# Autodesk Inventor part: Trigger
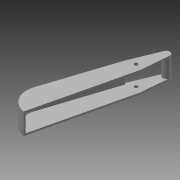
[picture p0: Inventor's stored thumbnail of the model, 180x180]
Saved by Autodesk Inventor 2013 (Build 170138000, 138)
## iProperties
Created: 2009-03
Part Number: Trigger
Document SubType Name: Modeling
Designer: tangg
Density: 7.85 g/cm^3
Material: Steel
Mass: 29.3702 g
Surface Area: 74.34 cm^2
Volume: 3.74142 cm^3
Author: tangg
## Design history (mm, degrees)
sketch "Sketch1"
  geometry: L1 (5, 0)-(6.989, 22.739); L2 (4, 23)-(0, 0); L3 (0, 0)-(-14.032, -80.685); L4 (-18.316, -17.771)-(-22.76, -43.324); L5 (-27.357, -57.698)-(-8.643, 0); L6 (-8.643, 0)-(1.223, 24.135); L7 (-13.913, -80)-(5, 0); A1 r 3 centre (4, 23) between (3.891, 20.002) and (3.827, 20.005); A2 r 17.238 centre (-10.959, -63.016) between (-27.357, -57.698) and (-13.913, -80); 1 further point
  constraints: 14 end point, 6 point on circle, 3 tangent, 2 centre point, 2 horizontal alignment, 2 point on line, 1 coincident, 1 collinear
  dimensions: "d6" = 6 diameter of A1; "d11" = 15 distance between parallel lines of L3 L4; "d23" = 23 vertical distance of point (0, 0) L2.start; "d24" = 8 distance from line of L6 point (0, 0); "d26" = 4 horizontal distance of point (0, 0) L2.start; "d32" = 5 distance of L1.start point (0, 0); "d36" = 80 vertical distance of point (0, 0) L7.start
extrude "Extrusion1" new body sketch "Sketch1" stored distance "d0" = 18; taper "d1" = 0 deg
shell "Shell6" dims "d31" = 1.5
sketch "Sketch2"
  geometry: L1 (4, 23)-(0, 0); C1 r 3 at (4, 23); A1 r 3 centre (4, 23) between (6.989, 22.739) and (1.223, 24.135) reference
  constraints: 2 end point, 1 centre point, 1 coincident, 1 point on line
  dimensions: "d22" = 6 diameter of C1; "d37" = 0 distance of C1.centre L1.start
extrude "Extrusion2" join sketch "Sketch2" stored distance "d14" = 10; taper "d15" = 0 deg
sketch "Sketch3"
  geometry: L1 (4, 23)-(0, 0); C1 r 1.5 at (-1, 2.5); A1 r 3 centre (4, 23) between (7, 23.027) and (2.132, 25.347); A2 r 3 centre (4, 23) between (6.989, 22.739) and (1.223, 24.135) reference
  constraints: 2 centre point, 2 concentric, 2 end point, 2 point on circle
  dimensions: "d33" = 3 diameter of C1; "d34" = 1 horizontal distance of L1.end C1.centre; "d35" = 2.5 vertical distance of L1.end C1.centre
extrude "Extrusion3" cut sketch "Sketch3" stored distance "d18" = 10; taper "d19" = 0 deg
sketch "Sketch4"
  geometry: L1 (1.5, 20.181)-(16.5, 20.181); L2 (16.5, 20.181)-(16.5, 0); L3 (16.5, 0)-(1.5, 0); L4 (1.5, 0)-(1.5, 20.181); L5 (0, 0)-(18, 0) reference; L6 (18, -60.489)-(18, 0) reference; L7 (0, 0)-(18, 0) reference; L8 (0, 0)-(0, -60.489) reference; L9 (0, -60.489)-(18, -60.489) reference; 1 further point
  constraints: 8 end point, 2 parallel, 1 collinear, 1 horizontal, 1 perpendicular
extrude "Extrusion4" cut sketch "Sketch4" stored distance "d38" = 10; taper "d39" = 0 deg
body "Solid1"
node "Projected Loop1"
